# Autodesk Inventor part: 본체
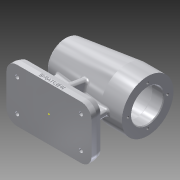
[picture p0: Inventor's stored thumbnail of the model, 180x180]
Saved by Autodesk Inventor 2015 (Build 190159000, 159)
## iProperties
Created: 2017-01
Part Number: 본체
Material: 알루미늄 6061
Document SubType Name: Modeling
Designer: Administrator
Mass: 793.172 g
Surface Area: 661.111 cm^2
Volume: 293.767 cm^3
Density: 2.7 g/cm^3
Appearance: 알루미늄 - 평지
Author: Administrator
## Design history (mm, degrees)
sketch "스케치1"
  geometry: 1 further point
sketch "스케치2"
  geometry: 1 further point
sketch "스케치3"
  geometry: L1 (-56, -35)-(56, -35); L2 (56, -35)-(56, 35); L3 (56, 35)-(-56, 35); L4 (-56, 35)-(-56, -35); L5 (-56, -35)-(56, 35); L6 (56, -35)-(-56, 35); 1 further point
  constraints: 12 end point, 2 midpoint, 2 parallel, 1 horizontal, 1 perpendicular
  dimensions: "d0" = 112 distance of L3.end L2.end; "d1" = 70 distance of L2.end L1.end
extrude "돌출1" new body sketch "스케치3" distance "d2" = 7; taper "d3" = 0 deg
sketch "스케치4"
  geometry: 1 further point
sketch "스케치5"
  geometry: L1 (42, 35)-(-42, 35); L2 (-56, 21)-(-56, -21); L3 (-42, -35)-(42, -35); L4 (56, -21)-(56, 21); L5 (56, 35)-(-56, -35); L6 (-56, 35)-(56, -35); A1 r 14 centre (-42, 21) between (-42, 35) and (-56, 21); A2 r 14 centre (-42, -21) between (-56, -21) and (-42, -35); A3 r 14 centre (42, -21) between (42, -35) and (56, -21); A4 r 14 centre (42, 21) between (56, 21) and (42, 35); 1 further point
  constraints: 12 end point, 8 point on circle, 8 point on line, 8 tangent, 4 centre point, 3 equal radius, 2 midpoint, 2 parallel, 1 horizontal, 1 perpendicular
  dimensions: "d4" = 14 radius of A1
extrude "돌출2" join sketch "스케치5" distance "d5" = 7; taper "d6" = -15 deg
fillet "모깎기1" dims "d7" = 14
sketch "스케치6"
  geometry: L1 (56, 35)-(-56, 35); L2 (-56, 35)-(-56, -35); L3 (-56, -35)-(56, -35); L4 (56, -35)-(56, 35); L5 (56, 35)-(-56, -35); L6 (-56, 35)-(56, -35); C1 r 2.5 at (-42, -21); C2 r 2.5 at (42, -21); C3 r 2.5 at (-42, 21); C4 r 2.5 at (42, 21); 1 further point
  constraints: 12 end point, 4 centre point, 2 horizontal, 2 midpoint, 2 parallel, 1 perpendicular, 1 vertical, 6 other
  dimensions: "d8" = 5 diameter of C1; "d9" = 112 distance of L3.end L2.end; "d10" = 70 distance of L2.end L1.end; "d11" = 42 horizontal distance of point (0, 0) C1.centre; "d12" = 21 vertical distance of point (0, 0) C1.centre; "d15" = 84 distance of C1.centre C2.centre; "d18" = 42 distance of C1.centre C3.centre
extrude "돌출3" cut sketch "스케치6" stored distance "d21" = 7; taper "d22" = 0 deg
sketch "스케치8"
  geometry: L1 (38, -4)-(-38, -4); L2 (-38, -4)-(-38, 4); L3 (-38, 4)-(38, 4); L4 (38, 4)-(38, -4); L5 (38, -4)-(-38, 4); L6 (-38, -4)-(38, 4); L7 (-56, 21)-(-56, -21) reference; 1 further point
  constraints: 12 end point, 2 midpoint, 2 parallel, 1 horizontal, 1 perpendicular
  dimensions: "d34" = 8 distance of L1.end L2.end; "d35" = 18 distance between parallel lines of L7 L2
sketch "스케치9"
  geometry: L1 (56, 108)-(56, 74); L2 (56, 74)-(-56, 74); L3 (56, 108)-(28, 108); L4 (28, 108)-(-52.27, 98.144); L5 (-42, 0)-(42, 0) reference; L6 (56, 0)-(56, 7) reference; A1 r 80 centre (24, 74) between (-52.27, 98.144) and (-56, 74); 1 further point
  constraints: 8 end point, 2 point on circle, 1 centre point, 1 horizontal, 1 perpendicular, 1 point on line, 1 vertical
  dimensions: "d36" = 28 distance of L1.start L3.end; "d37" = 34 distance between parallel lines of L2 L3; "d38" = 74 distance between parallel lines of L5 L2; "d39" = 0 distance from line of L6 L1.end; "d40" = 7 deg angle of L3 L4; "d42" = 112 distance from line of L2.end L1; "d43" = 80 radius of A1
revolve "회전1" sketch "스케치9" stored, may be unused: angle "d44" = 90 deg
extrude "돌출5" join sketch "스케치8" stored distance "d45" = 4; taper "d46" = 0 deg
fillet "모깎기2" dims "d47" = 3
sketch "스케치10"
  geometry: L1 (14, -4)-(40.236, -4) reference; L2 (40.236, -4)-(48.415, -4) reference; L3 (40.236, -4)-(48.415, -4) reference; L4 (48.415, 4)-(40.236, 4) reference; L5 (14, -21)-(14, -33.124) reference; L6 (14, -21)-(14, 21) reference; L7 (59.846, -14.916)-(14, -23); L8 (0, -35)-(7, -35) reference; C1 r 24.382 at (74, 0) reference; A1 r 34 centre (74, 0) between (40.236, -4) and (40.236, 4) reference; A2 r 25.896 centre (74, 0) between (48.415, 4) and (48.415, -4) reference; 1 further point
  constraints: 2 end point, 1 point on line
  dimensions: "d48" = 100 deg angle of L5 L7; "d49" = 12 distance from line of L7.end L8
feature "리브1" sketch "스케치10" dims "d50" = 1, "d51" = 8, "d52" = 0, "d53" = 0, "d54" = 1, "d55" = 1
sketch "스케치11" dims "d56" = 10
  geometry: L1 (46.33, 23.5)-(46.33, 18.5); L2 (46.33, 18.5)-(42, 16); L3 (42, 16)-(37.67, 18.5); L4 (37.67, 18.5)-(37.67, 23.5); L5 (37.67, 23.5)-(42, 26); L6 (42, 26)-(46.33, 23.5); L7 (42, 35)-(-42, 35) reference; L8 (-42, 35)-(-42, 33.124) reference; L9 (-42, 33.124)-(42, 33.124) reference; L10 (42, 35)-(42, 33.124) reference; L11 (54.124, 21)-(54.124, -21) reference; L12 (56, -21)-(54.124, -21) reference; L13 (56, -21)-(56, 21) reference; L14 (56, 21)-(54.124, 21) reference; L15 (-46.33, 18.5)-(-46.33, 23.5); L16 (-46.33, 23.5)-(-42, 26); L17 (-42, 26)-(-37.67, 23.5); L18 (-37.67, 23.5)-(-37.67, 18.5); L19 (-37.67, 18.5)-(-42, 16); L20 (-42, 16)-(-46.33, 18.5); L21 (37.67, -23.5)-(37.67, -18.5); L22 (37.67, -18.5)-(42, -16); L23 (42, -16)-(46.33, -18.5); L24 (46.33, -18.5)-(46.33, -23.5); L25 (46.33, -23.5)-(42, -26); L26 (42, -26)-(37.67, -23.5); L27 (-46.33, -23.5)-(-46.33, -18.5); L28 (-46.33, -18.5)-(-42, -16); L29 (-42, -16)-(-37.67, -18.5); L30 (-37.67, -18.5)-(-37.67, -23.5); L31 (-37.67, -23.5)-(-42, -26); L32 (-42, -26)-(-46.33, -23.5); C1 r 2.5 at (42, 21) reference; 3 further points
  constraints: 48 end point, 2 coincident, 1 horizontal, 1 vertical, 52 other
  dimensions: "d57" = 4.33013 horizontal distance of C1.centre L1.end; "d60" = 84 distance of L3.end L15.start; "d63" = 42 distance of L3.end L21.start
extrude "돌출6" cut sketch "스케치11" distance "d66" = 4; taper "d67" = 0 deg
sketch "스케치12"
  geometry: L1 (-50, 74)-(56, 74); L2 (56, 74)-(56, 95); L3 (56, 95)-(41, 95); L4 (41, 95)-(41, 98); L5 (41, 98)-(-13, 98); L6 (-13, 98)-(-13, 95); L7 (-13, 95)-(-25, 95); L8 (-25, 95)-(-25, 91.5); L9 (-25, 91.5)-(-43, 91.5); L10 (-43, 91.5)-(-43, 90); L11 (-47, 90)-(-43, 90); L12 (56, 7)-(56, 0) reference; L13 (-47, 90)-(-47, 84.5); L14 (-47, 84.5)-(-50, 84.5); L15 (-50.331, 98.382)-(-50.331, 49.618) reference; L16 (-50, 84.5)-(-50, 74); 1 further point
  constraints: 28 end point, 10 perpendicular, 2 point on line, 1 horizontal, 1 vertical
  dimensions: "d68" = 0 distance between parallel lines of L12 L2; "d69" = 74 distance from line of point (0, 0) L1; "d70" = 21 distance between parallel lines of L1 L3; "d71" = 24 distance between parallel lines of L1 L5; "d72" = 15 distance of L2.end L3.end; "d73" = 54 distance of L4.end L5.end; "d74" = 12 distance of L6.end L7.end; "d75" = 17.5 distance between parallel lines of L1 L9; "d76" = 18 distance of L8.end L9.end; "d77" = 4 distance of L11.start L10.end; "d78" = 16 distance between parallel lines of L1 L11; "d79" = 3 distance of L13.end L14.end; "d80" = 10.5 distance between parallel lines of L1 L14
revolve "회전2" sketch "스케치12" stored, may be unused: angle "d81" = 90 deg
fillet "모깎기3" dims "d82" = 3
fillet "모깎기4" dims "d83" = 0.3
fillet "모깎기5" dims "d84" = 3
chamfer "모따기1" distance "d85" = 1; stored, may be unused: second distance "d86" = 2, angle "d87" = 45 deg
fillet "모깎기6" dims "d88" = 3
fillet "모깎기7" dims "d89" = 3
fillet "모깎기8" dims "d90" = 3
fillet "모깎기9" dims "d91" = 3
sketch "스케치13" dims "d94" = 52
  geometry: L1 (-21, -74)-(21, -74) reference; 5 further points
  constraints: 4 vertical alignment, 2 midpoint, 2 other
  dimensions: "d93" = 74 distance of point (0, -74) point (0, 0)
hole "구멍1" sketch "스케치13" at (0, 26) diameter "d95" = 3.242; stored, may be unused: countersink angle "d99" = 90 deg, drill point angle "d101" = 118 deg; dims "d96" = 8, "d97" = 4, "d98" = 2, "d100" = 11
node "작업 평면2"
sketch "스케치14"
  geometry: L1 (56, 0)-(42, 0) reference; L2 (56, 0)-(56, 7) reference; 2 further points
  constraints: 1 other
  dimensions: "d108" = 56 horizontal distance of L1.start point (0, 4); "d109" = 4 vertical distance of L1.start point (0, 4)
feature "엠보싱1" sketch "스케치14" dims "d110" = 0.5, "d111" = 0
fillet "모깎기10" dims "d112" = 1
node "솔리드1"
mirror "대칭1"
pattern_circular "원형 패턴1" dims angle "d103" = 360 deg
node "투영된 루프1"
node "작업 평면1"
node "투영된 루프2"
node "투영된 루프3"
